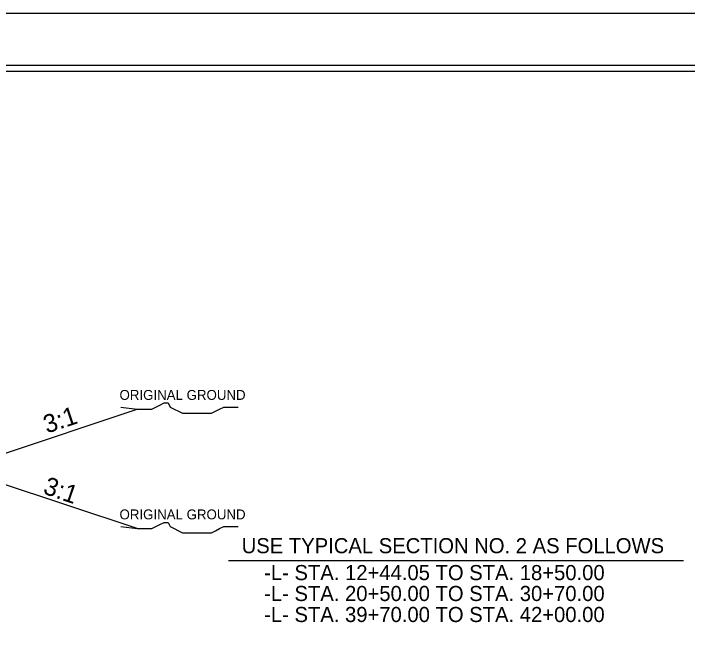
# Model space of a CAD drawing. Extents: x 957297 to 961629, y 830661 to 840840.
# Drawn here: x 959885.8 to 960176, y 839346.6 to 839615.4 of the extents above; entities that cross this region are included whole.
import ezdxf

# ---------------------------------------------------------------- set-up
doc = ezdxf.new("R2010")
doc.units = 0
for name, color, linetype in [('Old_Level_1', 7, 'Continuous'), ('Old_Level_21', 7, 'Continuous'), ('Old_Level_3', 7, 'Continuous'), ('Sheet Plot Border Inside CELL', 7, 'Continuous'), ('Sheet Plot Border Outside CELL', 7, 'Continuous'), ('Sheet Typical CELL', 7, 'Continuous')]:
    doc.layers.add(name, color=color, linetype=linetype)

msp = doc.modelspace()

# ---------------------------------------------------------------- linework, layer by layer
at = {"layer": 'Old_Level_1'}
for p, q in [((959861.91, 839419.21), (959939.1, 839444.94)), ((959939.1, 839393.48), (959861.91, 839419.21)), ((959978.32, 839379.75), (960174.26, 839379.75))]:
    msp.add_line(p, q, dxfattribs=at)
at = {"layer": 'Old_Level_21'}
for points in [[(959932, 839445.82), (959939.1, 839444.94), (959940.87, 839444.94), (959943.53, 839444.94), (959945.31, 839444.94), (959947.08, 839445.82), (959948.85, 839446.72), (959950.62, 839447.6), (959952.4, 839447.6), (959953.3, 839445.82), (959955.06, 839444.94), (959956.84, 839444.04), (959958.61, 839443.17), (959960.38, 839443.17), (959962.15, 839443.17), (959963.93, 839443.17), (959965.7, 839443.17), (959967.48, 839443.17), (959969.25, 839443.17), (959971.02, 839443.17), (959972.79, 839444.04), (959974.56, 839444.94), (959976.33, 839445.82), (959979.01, 839445.82), (959980.78, 839445.82), (959982.55, 839445.82)], [(959932, 839394.36), (959939.1, 839393.48), (959940.87, 839393.48), (959943.53, 839393.48), (959945.31, 839393.48), (959947.08, 839394.36), (959948.85, 839395.25), (959950.62, 839396.14), (959952.4, 839396.14), (959953.3, 839394.36), (959955.06, 839393.48), (959956.84, 839392.58), (959958.61, 839391.71), (959960.38, 839391.71), (959962.15, 839391.71), (959963.93, 839391.71), (959965.7, 839391.71), (959967.48, 839391.71), (959969.25, 839391.71), (959971.02, 839391.71), (959972.79, 839392.58), (959974.56, 839393.48), (959976.33, 839394.36), (959979.01, 839394.36), (959980.78, 839394.36), (959982.55, 839394.36)]]:
    msp.add_lwpolyline(points, dxfattribs=at)
at = {"layer": 'Sheet Plot Border Inside CELL'}
msp.add_lwpolyline([(960390.3, 839592.94), (958723.8, 839592.94), (958723.8, 838537.84), (960390.3, 838537.84)], close=True, dxfattribs=at)
at = {"layer": 'Sheet Plot Border Outside CELL'}
msp.add_lwpolyline([(960394.8, 839615.39), (958710.8, 839615.39), (958710.8, 838515.39), (960394.8, 838515.39)], close=True, dxfattribs=at)
at = {"layer": 'Sheet Typical CELL'}
msp.add_lwpolyline([(960377.8, 839590.39), (958877.8, 839590.39), (958877.8, 838540.39), (960377.8, 838540.39)], close=True, dxfattribs=at)

# ---------------------------------------------------------------- texts
at = {"layer": 'Old_Level_1'}
for s, p in [('USE TYPICAL SECTION NO. 2 AS FOLLOWS', (959984.05, 839382.88)), ('-L- STA. 12+44.05 TO STA. 18+50.00', (959993.73, 839371.29)), ('-L- STA. 20+50.00 TO STA. 30+70.00', (959993.73, 839362.29)), ('-L- STA. 39+70.00 TO STA. 42+00.00', (959993.73, 839353.24))]:
    msp.add_text(s, height=6.5088, dxfattribs=at).set_placement(p)
at = {"layer": 'Old_Level_21'}
for p in [(959931.46, 839448.93), (959931.46, 839397.47)]:
    msp.add_text('ORIGINAL GROUND', height=4.2722, dxfattribs=at).set_placement(p)
at = {"layer": 'Old_Level_3'}
for rotation, p in [(18.4348, (959900.21, 839434.39)), (341.0454, (959898.15, 839408.7))]:
    msp.add_text('3:1', height=7.801, rotation=rotation, dxfattribs=at).set_placement(p)

doc.saveas('drawing.dxf')
